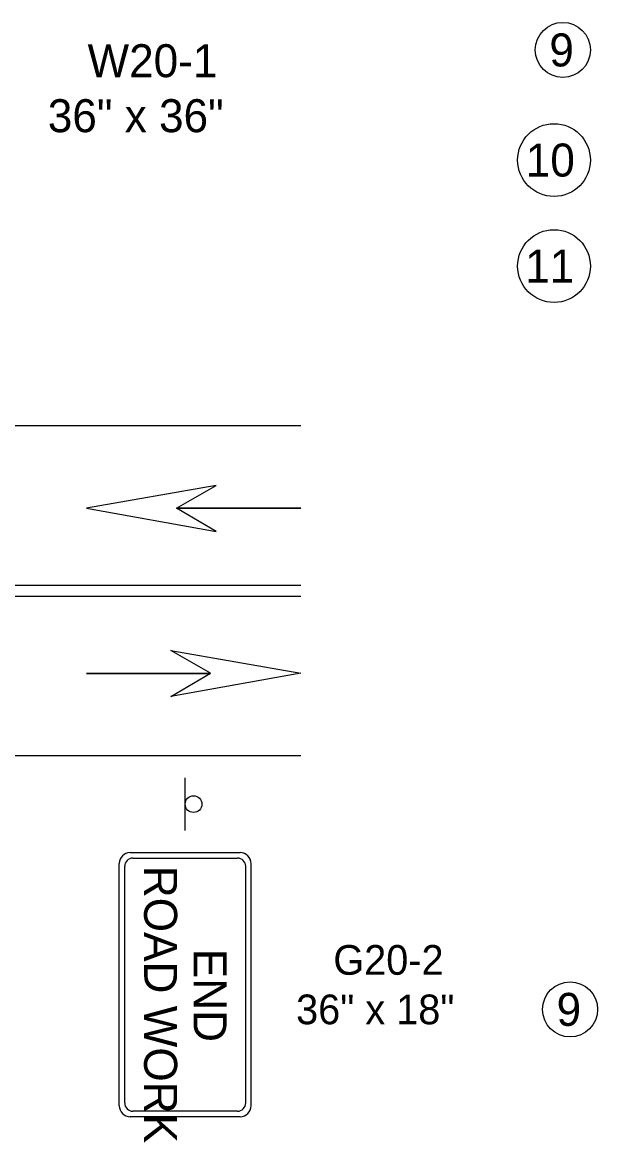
# Model space of a CAD drawing. Extents: x 49991.4 to 50021, y 49987.6 to 50011.4.
# Drawn here: x 50003.961 to 50005.008, y 49992.437 to 49994.474 of the extents above; entities that cross this region are included whole.
import ezdxf

# ---------------------------------------------------------------- set-up
doc = ezdxf.new("R2010")
doc.units = 0
for name, color, linetype in [('Level 1', 7, 'Continuous'), ('Level 2', 7, 'Continuous'), ('Level 3', 7, 'Continuous')]:
    doc.layers.add(name, color=color, linetype=linetype)

# ---------------------------------------------------------------- blocks, each defined once
blk = doc.blocks.new('G20-2')
at = {"layer": 'Level 1'}
for p, q in [((0.2197, 0.1196), (-0.2203, 0.1196)), ((0.2147, 0.1096), (-0.2153, 0.1096)), ((-0.2403, -0.1004), (-0.2403, 0.0996)), ((-0.2303, -0.0954), (-0.2303, 0.0946)), ((0.2297, 0.0946), (0.2297, -0.0954)), ((0.2397, 0.0996), (0.2397, -0.1004)), ((0.2196, -0.1204), (-0.2204, -0.1204)), ((0.2147, -0.1104), (-0.2153, -0.1104))]:
    blk.add_line(p, q, dxfattribs=at)
for centre, radius, start, end in [((-0.2203, 0.0996), 0.02, 90, 180), ((-0.2153, 0.0946), 0.015, 90, 180), ((0.2147, 0.0946), 0.015, 360, 90), ((0.2197, 0.0996), 0.02, 360, 90), ((-0.2204, -0.1004), 0.02, 180, 270), ((-0.2153, -0.0954), 0.015, 180, 270), ((0.2147, -0.0954), 0.015, 270, 360), ((0.2196, -0.1004), 0.02, 270, 360)]:
    blk.add_arc(centre, radius, start, end, dxfattribs=at)
for s, p in [('END', (-0.0655, 0.015)), ('ROAD WORK', (-0.2162, -0.075))]:
    blk.add_text(s, height=0.06, rotation=360, dxfattribs=at).set_placement(p)

msp = doc.modelspace()

# ---------------------------------------------------------------- linework, layer by layer
at = {"layer": 'Level 1'}
for p, q in [((50004.4673, 49993.7404), (50002.6673, 49993.7404)), ((50004.4673, 49993.5905), (50004.2414, 49993.5905)), ((50004.4673, 49993.5901), (50004.2414, 49993.5901)), ((50004.4673, 49993.4504), (50002.6973, 49993.4504)), ((50004.4673, 49993.4304), (50002.6673, 49993.4304)), ((50004.0772, 49993.2905), (50004.3031, 49993.2905)), ((50004.0772, 49993.2901), (50004.3031, 49993.2901)), ((50004.4673, 49993.1404), (50002.6673, 49993.1404)), ((50004.2571, 49993.0044), (50004.2571, 49993.1004))]:
    msp.add_line(p, q, dxfattribs=at)
for points in [[(50004.3137, 49993.6321), (50004.0772, 49993.5905), (50004.3137, 49993.5485), (50004.2415, 49993.5905)], [(50004.2308, 49993.3321), (50004.4673, 49993.2905), (50004.2308, 49993.2485), (50004.303, 49993.2905)]]:
    msp.add_lwpolyline(points, close=True, dxfattribs=at)
msp.add_circle((50004.2722, 49993.0525), 0.0152, dxfattribs=at)
at = {"layer": 'Level 2'}
for centre, radius in [((50004.9444, 49994.4241), 0.0501), ((50004.9283, 49994.2238), 0.0662), ((50004.9283, 49994.031), 0.0662), ((50004.9576, 49992.6792), 0.0501)]:
    msp.add_circle(centre, radius, dxfattribs=at)

# ---------------------------------------------------------------- block references
at = {"layer": 'Level 3', "xscale": 1.001, "yscale": 1.001, "rotation": -90.00000000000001}
msp.add_blockref('G20-2', (50004.2574, 49992.7239), dxfattribs=at)

# ---------------------------------------------------------------- texts
at = {"layer": 'Level 2'}
for s, height, p in [('9', 0.06, (50004.9198, 49994.3941)), ('10', 0.06006, (50004.8769, 49994.1938)), ('11', 0.06006, (50004.8759, 49994.0011)), ('G20-2', 0.054, (50004.5266, 49992.7422)), ('36" x 18"', 0.054, (50004.4589, 49992.6522)), ('9', 0.06, (50004.933, 49992.6492))]:
    msp.add_text(s, height=height, dxfattribs=at).set_placement(p)
for s, p in [('W20-1', (50004.0793, 49994.3745)), ('36" x 36"', (50004.007, 49994.2745))]:
    msp.add_text(s, height=0.06, rotation=360, dxfattribs=at).set_placement(p)

doc.saveas('drawing.dxf')
